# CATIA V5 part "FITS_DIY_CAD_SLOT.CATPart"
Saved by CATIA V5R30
Part number: FITS_DIY_CAD
Revision: 1
Definition: FITS_DIY_CAD
Nomenclature: FITS_DIY_CAD
Source: Unknown
Bounding box of the stored display mesh (mm): x 3364.428 to 3389.83, y -64.02 to 64.02, z 662.297 to 732.904
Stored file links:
  C:\Users\gmarsh66\Desktop\misc me\ford\fits accessories\misc\FITS_DIY_CAD_console.CATPart
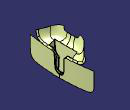
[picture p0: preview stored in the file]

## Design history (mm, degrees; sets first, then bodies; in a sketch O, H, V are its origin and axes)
Set1
  DatumSurface1
Body1 (main body)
